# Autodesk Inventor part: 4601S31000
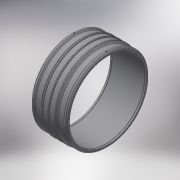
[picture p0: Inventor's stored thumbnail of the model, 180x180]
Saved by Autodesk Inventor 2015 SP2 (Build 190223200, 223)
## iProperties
Created: 2017-06
Part Number: 4601S31000
Material: Generic
Description: PLASSON SUPER LIGHTFIT 1000 MM
Document SubType Name: Modeling
Designer: KIM
Mass: 40474.6 g
Surface Area: 32331.6 cm^2
Volume: 40474.6 cm^3
Density: 1 g/cm^3
Appearance: Default
Author: KIM
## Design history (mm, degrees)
derived "4601S3.ipt"
feature "Solid1::4601S3.ipt"
tag "TaggingFeature1"
body "Solid1"
other parameters: "d14" = 17.6296, "d19" = 3.52592, "d20" = 168 deg, "d22" = 1068, "d23" = 1085, "d24" = 1035.96, "d25" = 135 deg, "d26" = 176, "d27" = 135 deg, "d29" = 534, "d35" = 15, "d39" = 0, "d40" = 4, "d41" = 14, "d42" = 0, "d43" = 135 deg, "d44" = 48.4, "d45" = 17.6, "d46" = 17.6, "d47" = 17.6, "d48" = 1063.3, "d49" = 1085, "d50" = 5.425, "d51" = 6, "d52" = 0, "D_" = 1085, "A_" = 534, "d_2" = 12
